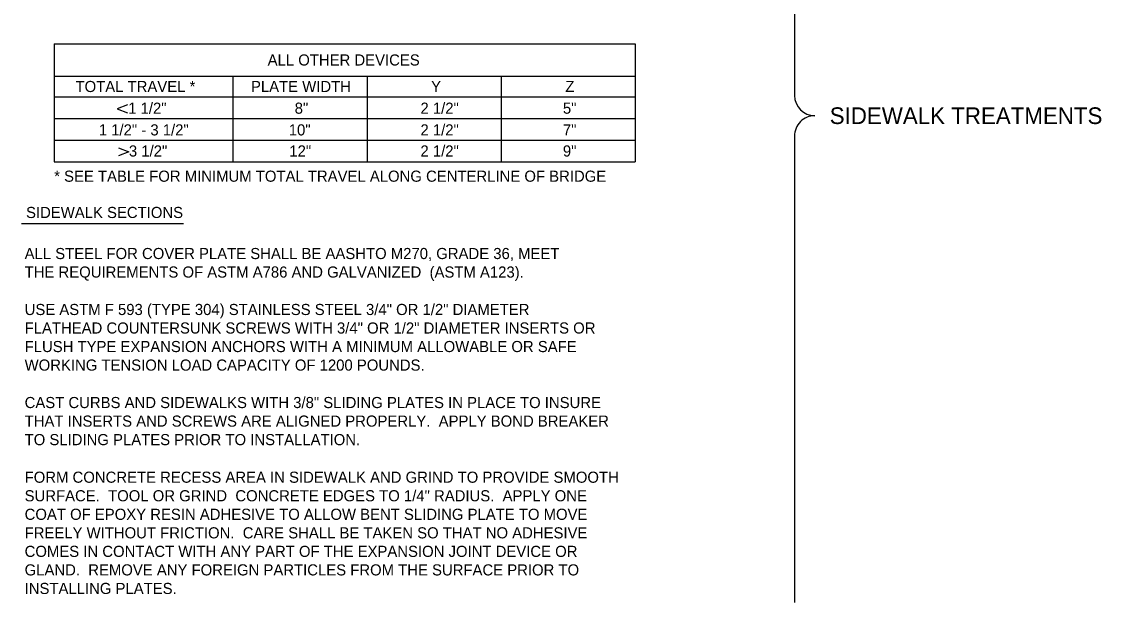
# Model space of a CAD drawing. Extents: x 19590 to 20151, y 19944 to 20103.
# Drawn here: x 19680.45 to 19728.76, y 20023.77 to 20049.76 of the extents above; entities that cross this region are included whole.
import ezdxf

# ---------------------------------------------------------------- set-up
doc = ezdxf.new("R2010")
doc.units = 0
doc.layers.add('DETAIL_TEXT_DIMEN_PR', color=7, linetype='Continuous')
doc.layers.add('Level 1', color=7, linetype='Continuous')

# ---------------------------------------------------------------- blocks, each defined once
blk = doc.blocks.new('TERM')
at = {"layer": 'DETAIL_TEXT_DIMEN_PR'}
for p, q in [((-0.0388, -0.01), (0, 0)), ((0, 0), (-0.0387, 0.01))]:
    blk.add_line(p, q, dxfattribs=at)

msp = doc.modelspace()

# ---------------------------------------------------------------- linework, layer by layer
at = {"layer": 'DETAIL_TEXT_DIMEN_PR'}
for p, q in [((19715.034, 20067.326), (19715.034, 20046.412)), ((19681.908, 20048.772), (19681.908, 20043.485)), ((19681.908, 20048.772), (19707.908, 20048.772)), ((19681.908, 20048.772), (19681.908, 20043.485)), ((19681.908, 20048.772), (19707.908, 20048.772)), ((19707.908, 20048.772), (19707.908, 20043.485)), ((19707.908, 20048.772), (19707.908, 20043.485)), ((19681.917, 20047.314), (19707.908, 20047.314)), ((19681.917, 20047.314), (19707.908, 20047.314)), ((19689.908, 20047.314), (19689.908, 20043.485)), ((19689.908, 20047.314), (19689.908, 20043.485)), ((19695.908, 20047.314), (19695.908, 20043.485)), ((19695.908, 20047.314), (19695.908, 20043.485)), ((19701.908, 20047.314), (19701.908, 20043.485)), ((19701.908, 20047.314), (19701.908, 20043.485)), ((19681.899, 20046.398), (19707.908, 20046.398)), ((19681.899, 20046.398), (19707.908, 20046.398)), ((19681.908, 20045.427), (19707.908, 20045.427)), ((19681.908, 20045.427), (19707.908, 20045.427)), ((19681.908, 20044.456), (19707.908, 20044.456)), ((19681.908, 20044.456), (19707.908, 20044.456)), ((19715.034, 20044.659), (19715.034, 20023.772)), ((19681.908, 20043.485), (19707.908, 20043.485)), ((19681.908, 20043.485), (19707.908, 20043.485)), ((19680.451, 20040.722), (19687.7, 20040.722)), ((19680.451, 20040.722), (19687.7, 20040.722))]:
    msp.add_line(p, q, dxfattribs=at)
for centre, radius, start, end in [((19715.944, 20046.46), 0.911, 180.0337, 270.0337), ((19715.944, 20044.639), 0.91, 89.9663, 180.0337)]:
    msp.add_arc(centre, radius, start, end, dxfattribs=at)

# ---------------------------------------------------------------- block references
at = {"layer": 'Level 1', "xscale": 12, "yscale": 18, "rotation": 180}
msp.add_blockref('TERM', (19684.72, 20045.851), dxfattribs=at)
msp.add_blockref('TERM', (19684.72, 20045.851), dxfattribs=at)
at = {"layer": 'Level 1', "xscale": 12, "yscale": -18}
msp.add_blockref('TERM', (19685.248, 20043.936), dxfattribs=at)
msp.add_blockref('TERM', (19685.248, 20043.936), dxfattribs=at)

# ---------------------------------------------------------------- texts
at = {"layer": 'DETAIL_TEXT_DIMEN_PR'}
for s, height, p in [('ALL OTHER DEVICES', 0.49762, (19691.46, 20047.794)), ('ALL OTHER DEVICES', 0.49762, (19691.46, 20047.794)), ('TOTAL TRAVEL *', 0.49762, (19682.864, 20046.607)), ('TOTAL TRAVEL *', 0.49762, (19682.864, 20046.607)), ('PLATE WIDTH', 0.49762, (19690.714, 20046.607)), ('PLATE WIDTH', 0.49762, (19690.714, 20046.607)), ('Y', 0.498, (19698.774, 20046.607)), ('Y', 0.498, (19698.774, 20046.607)), ('Z', 0.498, (19704.777, 20046.607)), ('Z', 0.498, (19704.777, 20046.607)), ('  1 1/2"', 0.4976, (19684.85, 20045.637)), ('  1 1/2"', 0.4976, (19684.85, 20045.637)), ('8"', 0.4976, (19692.67, 20045.637)), ('8"', 0.4976, (19692.67, 20045.637)), ('2 1/2"', 0.4976, (19698.297, 20045.637)), ('2 1/2"', 0.4976, (19698.297, 20045.637)), ('5"', 0.4976, (19704.67, 20045.637)), ('5"', 0.4976, (19704.67, 20045.637)), ('1 1/2" - 3 1/2"', 0.49762, (19683.905, 20044.666)), ('1 1/2" - 3 1/2"', 0.49762, (19683.905, 20044.666)), ('10"', 0.4976, (19692.405, 20044.666)), ('10"', 0.4976, (19692.405, 20044.666)), ('2 1/2"', 0.4976, (19698.297, 20044.666)), ('2 1/2"', 0.4976, (19698.297, 20044.666)), ('7"', 0.4976, (19704.67, 20044.666)), ('7"', 0.4976, (19704.67, 20044.666)), ('  3 1/2"', 0.4976, (19684.883, 20043.722)), ('  3 1/2"', 0.4976, (19684.883, 20043.722)), ('2 1/2"', 0.4976, (19698.297, 20043.722)), ('2 1/2"', 0.4976, (19698.297, 20043.722)), ('12"', 0.4976, (19692.43, 20043.722)), ('12"', 0.4976, (19692.43, 20043.722)), ('9"', 0.4976, (19704.67, 20043.722)), ('9"', 0.4976, (19704.67, 20043.722)), ('SIDEWALK SECTIONS', 0.49762, (19680.65, 20040.971)), ('SIDEWALK SECTIONS', 0.49762, (19680.65, 20040.971))]:
    msp.add_text(s, height=height, rotation=0, dxfattribs=at).set_placement(p)
for s, height, p in [('SIDEWALK TREATMENTS', 0.74643, (19716.608, 20045.176)), ('* SEE TABLE FOR MINIMUM TOTAL TRAVEL ALONG CENTERLINE OF BRIDGE', 0.49762, (19681.908, 20042.594)), ('* SEE TABLE FOR MINIMUM TOTAL TRAVEL ALONG CENTERLINE OF BRIDGE', 0.49762, (19681.908, 20042.594)), ('ALL STEEL FOR COVER PLATE SHALL BE AASHTO M270, GRADE 36, MEET', 0.49762, (19680.587, 20039.134)), ('ALL STEEL FOR COVER PLATE SHALL BE AASHTO M270, GRADE 36, MEET', 0.49762, (19680.587, 20039.134)), ('THE REQUIREMENTS OF ASTM A786 AND GALVANIZED  (ASTM A123).', 0.49762, (19680.587, 20038.305)), ('THE REQUIREMENTS OF ASTM A786 AND GALVANIZED  (ASTM A123).', 0.49762, (19680.587, 20038.305)), ('USE ASTM F 593 (TYPE 304) STAINLESS STEEL 3/4" OR 1/2" DIAMETER ', 0.49762, (19680.587, 20036.63)), ('USE ASTM F 593 (TYPE 304) STAINLESS STEEL 3/4" OR 1/2" DIAMETER ', 0.49762, (19680.587, 20036.63)), ('FLATHEAD COUNTERSUNK SCREWS WITH 3/4" OR 1/2" DIAMETER INSERTS OR ', 0.49762, (19680.587, 20035.801)), ('FLATHEAD COUNTERSUNK SCREWS WITH 3/4" OR 1/2" DIAMETER INSERTS OR ', 0.49762, (19680.587, 20035.801)), ('FLUSH TYPE EXPANSION ANCHORS WITH A MINIMUM ALLOWABLE OR SAFE ', 0.49762, (19680.587, 20034.972)), ('FLUSH TYPE EXPANSION ANCHORS WITH A MINIMUM ALLOWABLE OR SAFE ', 0.49762, (19680.587, 20034.972)), ('WORKING TENSION LOAD CAPACITY OF 1200 POUNDS.', 0.49762, (19680.587, 20034.142)), ('WORKING TENSION LOAD CAPACITY OF 1200 POUNDS.', 0.49762, (19680.587, 20034.142)), ('CAST CURBS AND SIDEWALKS WITH 3/8" SLIDING PLATES IN PLACE TO INSURE ', 0.49762, (19680.587, 20032.466)), ('CAST CURBS AND SIDEWALKS WITH 3/8" SLIDING PLATES IN PLACE TO INSURE ', 0.49762, (19680.587, 20032.466)), ('THAT INSERTS AND SCREWS ARE ALIGNED PROPERLY.  APPLY BOND BREAKER', 0.49762, (19680.587, 20031.636)), ('THAT INSERTS AND SCREWS ARE ALIGNED PROPERLY.  APPLY BOND BREAKER', 0.49762, (19680.587, 20031.636)), ('TO SLIDING PLATES PRIOR TO INSTALLATION.', 0.49762, (19680.587, 20030.807)), ('TO SLIDING PLATES PRIOR TO INSTALLATION.', 0.49762, (19680.587, 20030.807)), ('FORM CONCRETE RECESS AREA IN SIDEWALK AND GRIND TO PROVIDE SMOOTH ', 0.49762, (19680.587, 20029.125)), ('FORM CONCRETE RECESS AREA IN SIDEWALK AND GRIND TO PROVIDE SMOOTH ', 0.49762, (19680.587, 20029.125)), ('SURFACE.  TOOL OR GRIND  CONCRETE EDGES TO 1/4" RADIUS.  APPLY ONE ', 0.49762, (19680.587, 20028.295)), ('SURFACE.  TOOL OR GRIND  CONCRETE EDGES TO 1/4" RADIUS.  APPLY ONE ', 0.49762, (19680.587, 20028.295)), ('COAT OF EPOXY RESIN ADHESIVE TO ALLOW BENT SLIDING PLATE TO MOVE ', 0.49762, (19680.587, 20027.466)), ('COAT OF EPOXY RESIN ADHESIVE TO ALLOW BENT SLIDING PLATE TO MOVE ', 0.49762, (19680.587, 20027.466)), ('FREELY WITHOUT FRICTION.  CARE SHALL BE TAKEN SO THAT NO ADHESIVE ', 0.49762, (19680.587, 20026.636)), ('FREELY WITHOUT FRICTION.  CARE SHALL BE TAKEN SO THAT NO ADHESIVE ', 0.49762, (19680.587, 20026.636)), ('COMES IN CONTACT WITH ANY PART OF THE EXPANSION JOINT DEVICE OR ', 0.49762, (19680.587, 20025.807)), ('COMES IN CONTACT WITH ANY PART OF THE EXPANSION JOINT DEVICE OR ', 0.49762, (19680.587, 20025.807)), ('GLAND.  REMOVE ANY FOREIGN PARTICLES FROM THE SURFACE PRIOR TO ', 0.49762, (19680.587, 20024.978)), ('GLAND.  REMOVE ANY FOREIGN PARTICLES FROM THE SURFACE PRIOR TO ', 0.49762, (19680.587, 20024.978)), ('INSTALLING PLATES.', 0.49762, (19680.587, 20024.148)), ('INSTALLING PLATES.', 0.49762, (19680.587, 20024.148))]:
    msp.add_text(s, height=height, dxfattribs=at).set_placement(p)

doc.saveas('drawing.dxf')
